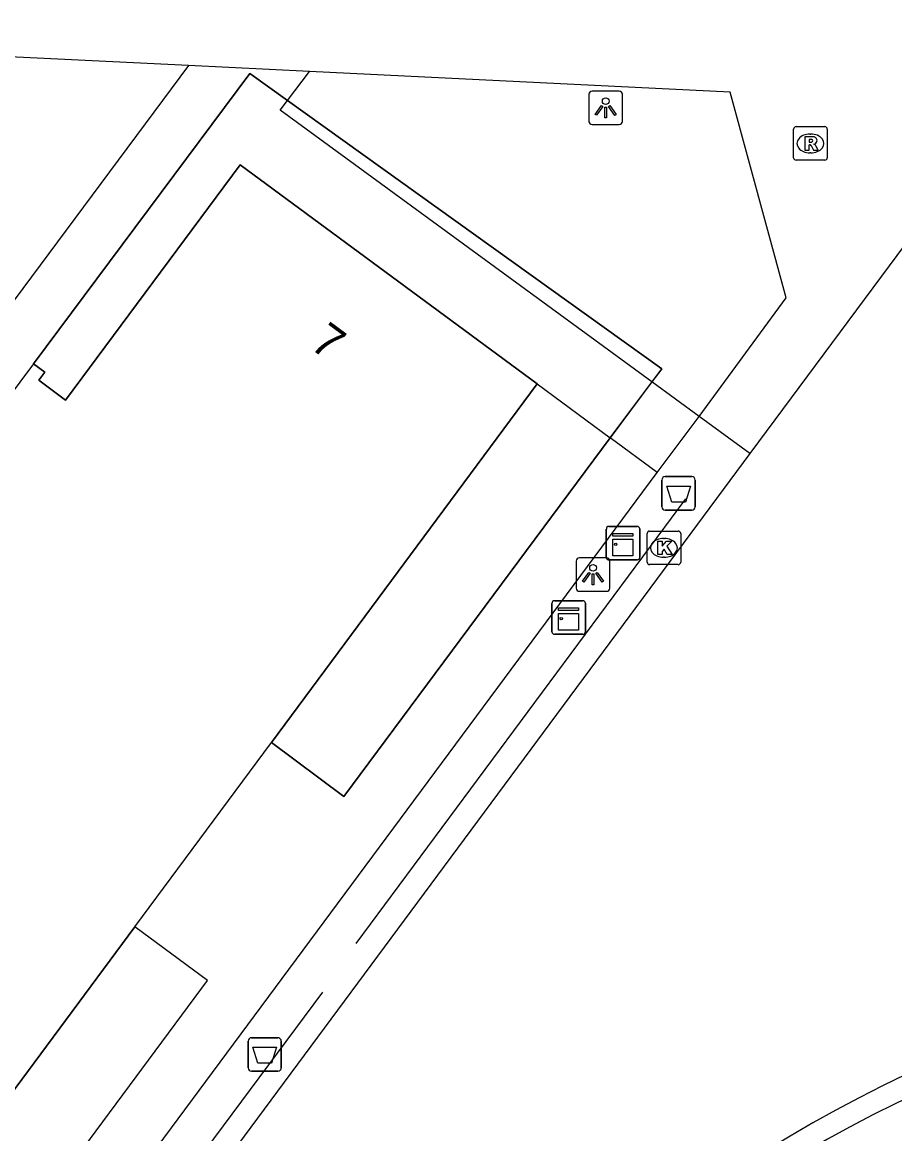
# Model space of a CAD drawing. Extents: x 161761 to 162722, y 384793 to 385405.
# Drawn here: x 162403.91 to 162429.91, y 385002.61 to 385035.74 of the extents above; entities that cross this region are included whole.
import ezdxf

# ---------------------------------------------------------------- set-up
doc = ezdxf.new("R2010")
doc.units = 0
for name, color, linetype in [('IMGEO_Afvalbak', 7, 'Continuous'), ('IMGEO_Groenvoorziening', 7, 'Continuous'), ('IMGEO_Hek', 7, 'Continuous'), ('IMGEO_Kast', 7, 'Continuous'), ('IMGEO_Kolk', 7, 'Continuous'), ('IMGEO_Lichtpunt', 7, 'Continuous'), ('IMGEO_Pand', 7, 'Continuous'), ('IMGEO_Pand_nummerreeks', 7, 'Continuous'), ('IMGEO_Pand_overbouw', 7, 'Continuous'), ('IMGEO_Rioolput', 7, 'Continuous'), ('IMGEO_Voetpad_open', 7, 'Continuous')]:
    doc.layers.add(name, color=color, linetype=linetype)

msp = doc.modelspace()

# ---------------------------------------------------------------- linework, layer by layer
at = {"layer": 'IMGEO_Afvalbak'}
for p, q in [((162422.972, 385021.294), (162422.972, 385022.094)), ((162422.972, 385022.094), (162422.972, 385021.294)), ((162423.072, 385022.194), (162423.862, 385022.194)), ((162423.862, 385022.194), (162423.072, 385022.194)), ((162423.962, 385022.094), (162423.962, 385021.294)), ((162423.962, 385021.294), (162423.962, 385022.094)), ((162423.862, 385021.194), (162423.072, 385021.194)), ((162423.072, 385021.194), (162423.862, 385021.194)), ((162410.637, 385004.571), (162410.637, 385005.371)), ((162410.637, 385005.371), (162410.637, 385004.571)), ((162410.737, 385005.471), (162411.527, 385005.471)), ((162411.527, 385005.471), (162410.737, 385005.471)), ((162411.627, 385005.371), (162411.627, 385004.571)), ((162411.627, 385004.571), (162411.627, 385005.371)), ((162411.527, 385004.471), (162410.737, 385004.471)), ((162410.737, 385004.471), (162411.527, 385004.471))]:
    msp.add_line(p, q, dxfattribs=at)
for points in [[(162423.115, 385021.908), (162423.819, 385021.908), (162423.67, 385021.438), (162423.264, 385021.438), (162423.115, 385021.908)], [(162410.78, 385005.185), (162411.484, 385005.185), (162411.335, 385004.715), (162410.929, 385004.715), (162410.78, 385005.185)]]:
    msp.add_lwpolyline(points, dxfattribs=at)
for centre, start, end in [((162423.072, 385022.094), 90, 180), ((162423.072, 385022.094), 90, 180), ((162423.862, 385022.094), 0, 90), ((162423.862, 385022.094), 360, 90), ((162423.072, 385021.294), 180, 270), ((162423.072, 385021.294), 180, 270), ((162423.862, 385021.294), 270, 0), ((162423.862, 385021.294), 270, 0), ((162410.737, 385005.371), 90, 180), ((162410.737, 385005.371), 90, 180), ((162411.527, 385005.371), 0, 90), ((162411.527, 385005.371), 360, 90), ((162410.737, 385004.571), 180, 270), ((162410.737, 385004.571), 180, 270), ((162411.527, 385004.571), 270, 0), ((162411.527, 385004.571), 270, 0)]:
    msp.add_arc(centre, 0.1, start, end, dxfattribs=at)
at = {"layer": 'IMGEO_Groenvoorziening'}
msp.add_lwpolyline([(162411.81, 385033.406), (162422.965, 385025.411), (162422.672, 385025.016)], dxfattribs=at)
at = {"layer": 'IMGEO_Hek'}
for points in [[(162423.674, 385021.538), (162413.845, 385008.282)], [(162412.851, 385006.833), (162386.424, 384971.276)]]:
    msp.add_lwpolyline(points, dxfattribs=at)
at = {"layer": 'IMGEO_Kast'}
for p, q in [((162421.315, 385019.788), (162421.315, 385020.629)), ((162421.315, 385020.629), (162421.315, 385019.788)), ((162421.39, 385020.713), (162422.231, 385020.713)), ((162422.231, 385020.713), (162421.39, 385020.713)), ((162422.315, 385020.638), (162422.315, 385019.797)), ((162422.315, 385019.797), (162422.315, 385020.638)), ((162422.24, 385019.713), (162421.399, 385019.713)), ((162421.399, 385019.713), (162422.24, 385019.713)), ((162419.692, 385017.571), (162419.692, 385018.412)), ((162419.692, 385018.412), (162419.692, 385017.571)), ((162419.767, 385018.496), (162420.608, 385018.496)), ((162420.608, 385018.496), (162419.767, 385018.496)), ((162420.692, 385018.421), (162420.692, 385017.58)), ((162420.692, 385017.58), (162420.692, 385018.421)), ((162420.617, 385017.496), (162419.776, 385017.496)), ((162419.776, 385017.496), (162420.617, 385017.496))]:
    msp.add_line(p, q, dxfattribs=at)
for points in [[(162421.51, 385020.503), (162422.11, 385020.503), (162422.11, 385020.418), (162421.51, 385020.418), (162421.51, 385020.503)], [(162421.51, 385020.328), (162422.11, 385020.328), (162422.11, 385019.839), (162421.51, 385019.839), (162421.51, 385020.328)], [(162419.887, 385018.286), (162420.487, 385018.286), (162420.487, 385018.201), (162419.887, 385018.201), (162419.887, 385018.286)], [(162419.887, 385018.111), (162420.487, 385018.111), (162420.487, 385017.622), (162419.887, 385017.622), (162419.887, 385018.111)]]:
    msp.add_lwpolyline(points, dxfattribs=at)
for centre in [(162421.594, 385020.177), (162419.971, 385017.96)]:
    msp.add_circle(centre, 0.0377, dxfattribs=at)
for centre, start, end in [((162421.393, 385020.635), 92.4484, 184.2845), ((162421.393, 385020.635), 92.4484, 184.2845), ((162422.237, 385020.635), 2.4484, 94.2845), ((162422.237, 385020.635), 2.4484, 94.2845), ((162421.393, 385019.791), 182.4484, 274.2845), ((162421.393, 385019.791), 182.4484, 274.2845), ((162422.237, 385019.791), 272.4484, 4.2845), ((162422.237, 385019.791), 272.4484, 4.2845), ((162419.77, 385018.418), 92.4484, 184.2845), ((162419.77, 385018.418), 92.4484, 184.2845), ((162420.614, 385018.418), 2.4484, 94.2845), ((162420.614, 385018.418), 2.4484, 94.2845), ((162419.77, 385017.574), 182.4484, 274.2845), ((162419.77, 385017.574), 182.4484, 274.2845), ((162420.614, 385017.574), 272.4484, 4.2845), ((162420.614, 385017.574), 272.4484, 4.2845)]:
    msp.add_arc(centre, 0.0779, start, end, dxfattribs=at)
at = {"layer": 'IMGEO_Kolk'}
for p, q in [((162422.531, 385019.645), (162422.531, 385020.497)), ((162422.606, 385020.571), (162423.458, 385020.571)), ((162423.532, 385020.497), (162423.532, 385019.645)), ((162423.019, 385020.351), (162423.044, 385020.351)), ((162423.042, 385019.791), (162423.017, 385019.791)), ((162423.458, 385019.571), (162422.606, 385019.571))]:
    msp.add_line(p, q, dxfattribs=at)
for points in [[(162422.531, 385019.645), (162422.531, 385020.497)], [(162422.606, 385020.571), (162423.458, 385020.571)], [(162423.532, 385020.497), (162423.532, 385019.645)], [(162422.852, 385020.271), (162422.975, 385020.271), (162422.975, 385020.12), (162423.105, 385020.271), (162423.269, 385020.271), (162423.123, 385020.12), (162423.276, 385019.871), (162423.124, 385019.871), (162423.039, 385020.035), (162422.975, 385019.968), (162422.975, 385019.871), (162422.852, 385019.871), (162422.852, 385020.271)], [(162423.458, 385019.571), (162422.606, 385019.571)]]:
    msp.add_lwpolyline(points, dxfattribs=at)
for centre, start, end in [((162422.608, 385020.495), 91.552, 178.448), ((162422.608, 385020.495), 91.552, 178.448), ((162423.456, 385020.495), 1.552, 88.448), ((162423.456, 385020.495), 1.552, 88.448), ((162422.608, 385019.647), 181.552, 268.448), ((162422.608, 385019.647), 181.552, 268.448), ((162423.456, 385019.647), 271.552, 358.448), ((162423.456, 385019.647), 271.552, 358.448)]:
    msp.add_arc(centre, 0.0765, start, end, dxfattribs=at)
for centre, major_axis, ratio, start_param, end_param in [((162423.018, 385020.071), (-0.387, 0.002), 0.722429, 4.712389, 7.853982), ((162423.043, 385020.071), (-0.39, 0.002), 0.717154, 1.570796, 4.712389)]:
    msp.add_ellipse(centre, major_axis=major_axis, ratio=ratio, start_param=start_param, end_param=end_param, dxfattribs=at)
at = {"layer": 'IMGEO_Lichtpunt'}
for p, q in [((162421.699, 385033.686), (162420.891, 385033.686)), ((162421.699, 385033.686), (162420.891, 385033.686)), ((162420.797, 385033.591), (162420.797, 385032.784)), ((162420.797, 385033.591), (162420.797, 385032.784)), ((162421.793, 385032.784), (162421.793, 385033.591)), ((162421.793, 385032.784), (162421.793, 385033.591)), ((162420.891, 385032.69), (162421.699, 385032.69)), ((162420.891, 385032.69), (162421.699, 385032.69)), ((162421.321, 385019.773), (162420.513, 385019.773)), ((162421.321, 385019.773), (162420.513, 385019.773)), ((162420.419, 385019.678), (162420.419, 385018.871)), ((162420.419, 385019.678), (162420.419, 385018.871)), ((162421.415, 385018.871), (162421.415, 385019.678)), ((162421.415, 385018.871), (162421.415, 385019.678)), ((162420.513, 385018.777), (162421.321, 385018.777)), ((162420.513, 385018.777), (162421.321, 385018.777))]:
    msp.add_line(p, q, dxfattribs=at)
for points in [[(162421.171, 385033.255), (162421.21, 385033.227), (162421.022, 385032.965), (162420.984, 385032.992), (162421.171, 385033.255)], [(162421.273, 385033.207), (162421.32, 385033.207), (162421.32, 385032.885), (162421.273, 385032.885), (162421.273, 385033.207)], [(162421.383, 385033.227), (162421.421, 385033.254), (162421.608, 385032.992), (162421.569, 385032.964), (162421.383, 385033.227)], [(162420.793, 385019.342), (162420.832, 385019.314), (162420.644, 385019.052), (162420.606, 385019.079), (162420.793, 385019.342)], [(162420.895, 385019.294), (162420.942, 385019.294), (162420.942, 385018.972), (162420.895, 385018.972), (162420.895, 385019.294)], [(162421.005, 385019.314), (162421.043, 385019.341), (162421.23, 385019.079), (162421.191, 385019.051), (162421.005, 385019.314)]]:
    msp.add_lwpolyline(points, dxfattribs=at)
for centre in [(162421.296, 385033.389), (162420.918, 385019.476)]:
    msp.add_circle(centre, 0.0994, dxfattribs=at)
for centre, start, end in [((162420.891, 385033.591), 90, 180), ((162420.891, 385033.591), 90, 180), ((162421.699, 385033.591), 0, 90), ((162421.699, 385033.591), 0, 90), ((162420.891, 385032.784), 180, 270), ((162420.891, 385032.784), 180, 270), ((162421.699, 385032.784), 270, 0), ((162421.699, 385032.784), 270, 360), ((162420.513, 385019.678), 90, 180), ((162420.513, 385019.678), 90, 180), ((162421.321, 385019.678), 0, 90), ((162421.321, 385019.678), 0, 90), ((162420.513, 385018.871), 180, 270), ((162420.513, 385018.871), 180, 270), ((162421.321, 385018.871), 270, 0), ((162421.321, 385018.871), 270, 360)]:
    msp.add_arc(centre, 0.0946, start, end, dxfattribs=at)
at = {"layer": 'IMGEO_Pand'}
for points in [[(162419.249, 385024.957), (162410.404, 385031.486), (162405.199, 385024.476), (162404.396, 385025.072), (162404.576, 385025.313), (162404.244, 385025.561)], [(162404.244, 385025.561), (162400.976, 385021.188)], [(162411.333, 385014.268), (162419.249, 385024.957)], [(162380.077, 384972.07), (162382.369, 384975.165), (162407.264, 385008.775), (162411.333, 385014.268)]]:
    msp.add_lwpolyline(points, dxfattribs=at)
at = {"layer": 'IMGEO_Pand_overbouw'}
for points in [[(162411.333, 385014.268), (162413.495, 385012.661), (162421.433, 385023.347), (162422.965, 385025.411), (162411.81, 385033.406), (162410.688, 385034.211), (162404.244, 385025.561), (162404.576, 385025.313), (162404.396, 385025.072), (162405.199, 385024.476), (162410.404, 385031.486), (162419.249, 385024.957)], [(162382.369, 384975.165), (162384.52, 384973.558), (162409.423, 385007.181), (162407.264, 385008.775)]]:
    msp.add_lwpolyline(points, close=True, dxfattribs=at)
at = {"layer": 'IMGEO_Rioolput'}
for p, q in [((162426.898, 385031.701), (162426.898, 385032.553)), ((162426.973, 385032.627), (162427.825, 385032.627)), ((162427.386, 385032.407), (162427.411, 385032.407)), ((162427.899, 385032.553), (162427.899, 385031.701)), ((162427.409, 385031.847), (162427.384, 385031.847)), ((162427.825, 385031.627), (162426.973, 385031.627))]:
    msp.add_line(p, q, dxfattribs=at)
for points in [[(162426.898, 385031.701), (162426.898, 385032.553)], [(162426.973, 385032.627), (162427.825, 385032.627)], [(162427.487, 385032.325), (162427.235, 385032.327), (162427.235, 385031.927)], [(162427.899, 385032.553), (162427.899, 385031.701)], [(162427.235, 385031.927), (162427.359, 385031.927), (162427.359, 385032.089), (162427.37, 385032.089)], [(162427.413, 385032.246), (162427.359, 385032.246), (162427.359, 385032.165)], [(162427.359, 385032.165), (162427.411, 385032.165)], [(162427.417, 385032.06), (162427.488, 385031.927), (162427.628, 385031.927), (162427.563, 385032.053)], [(162427.825, 385031.627), (162426.973, 385031.627)]]:
    msp.add_lwpolyline(points, dxfattribs=at)
for centre, radius, start, end in [((162426.975, 385032.551), 0.0765, 91.552, 178.448), ((162426.975, 385032.551), 0.0765, 91.552, 178.448), ((162427.486, 385032.215), 0.109, 350.3612, 89.416), ((162427.823, 385032.551), 0.0765, 1.552, 88.448), ((162427.823, 385032.551), 0.0765, 1.552, 88.448), ((162427.369, 385032.036), 0.0533, 26.0293, 88.6989), ((162427.395, 385032.354), 0.19, 274.7715, 282.9687), ((162427.419, 385032.15), 0.0964, 77.0061, 93.1865), ((162427.433, 385032.207), 0.0378, 276.6634, 79.6772), ((162427.484, 385032.215), 0.112, 277.5842, 350.9817), ((162427.468, 385032), 0.108, 29.5134, 73.7905), ((162426.975, 385031.703), 0.0765, 181.552, 268.448), ((162426.975, 385031.703), 0.0765, 181.552, 268.448), ((162427.823, 385031.703), 0.0765, 271.552, 358.448), ((162427.823, 385031.703), 0.0765, 271.552, 358.448)]:
    msp.add_arc(centre, radius, start, end, dxfattribs=at)
for centre, major_axis, ratio, start_param, end_param in [((162427.385, 385032.127), (-0.387, 0.002), 0.722429, 4.712389, 7.853982), ((162427.41, 385032.127), (-0.39, 0.002), 0.717154, 1.570796, 4.712389)]:
    msp.add_ellipse(centre, major_axis=major_axis, ratio=ratio, start_param=start_param, end_param=end_param, dxfattribs=at)
at = {"layer": 'IMGEO_Voetpad_open'}
for points in [[(162408.86, 385034.446), (162400.443, 385034.857), (162400.64, 385038.778), (162402.942, 385038.647)], [(162408.86, 385034.446), (162395.555, 385016.551)], [(162412.471, 385034.27), (162408.86, 385034.446)], [(162404.244, 385025.561), (162410.688, 385034.211), (162411.81, 385033.406)], [(162411.81, 385033.406), (162412.471, 385034.27)], [(162424.078, 385023.988), (162426.672, 385027.527), (162425.011, 385033.658), (162412.471, 385034.27)], [(162422.672, 385025.016), (162411.592, 385033.121), (162411.81, 385033.406)], [(162430.723, 385029.79), (162425.597, 385022.88)], [(162419.249, 385024.957), (162421.433, 385023.347)], [(162422.672, 385025.016), (162421.433, 385023.347)], [(162424.078, 385023.988), (162422.672, 385025.016)], [(162422.828, 385022.318), (162424.078, 385023.988)], [(162425.597, 385022.88), (162424.078, 385023.988)], [(162421.433, 385023.347), (162413.495, 385012.661), (162411.333, 385014.268)], [(162422.828, 385022.318), (162421.433, 385023.347)], [(162425.597, 385022.88), (162350.849, 384921.99), (162348.561, 384918.914)], [(162364.988, 384947.13), (162366.338, 384946.103), (162422.828, 385022.318)]]:
    msp.add_lwpolyline(points, dxfattribs=at)
for centre, radius, start, end in [((162447.215, 384968.187), 39.963, 56.3918, 127.5657), ((162447.022, 384968.408), 39.034, 56.0389, 127.2831)]:
    msp.add_arc(centre, radius, start, end, dxfattribs=at)

# ---------------------------------------------------------------- texts
at = {"layer": 'IMGEO_Pand_nummerreeks'}
msp.add_text('7', height=1, rotation=323.4627, dxfattribs=at).set_placement((162412.442, 385026.049))

doc.saveas('drawing.dxf')
